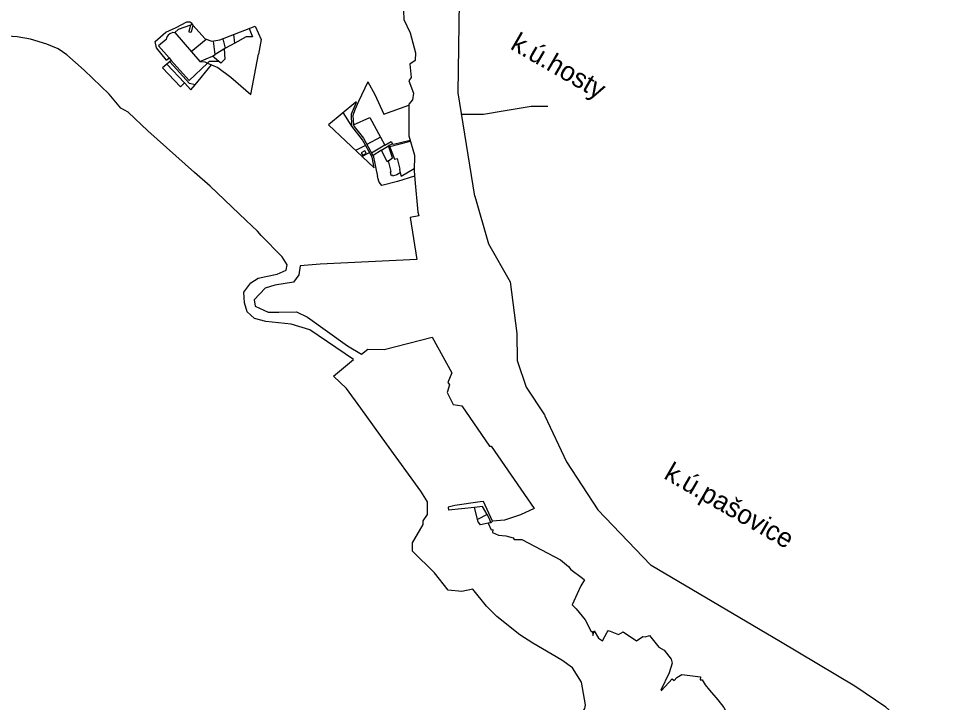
# Model space of a CAD drawing. Extents: x -764981 to -759318, y -1137368 to -1131930.
# Drawn here: x -762113 to -759967, y -1135485 to -1133883 of the extents above; entities that cross this region are included whole.
import ezdxf

# ---------------------------------------------------------------- set-up
doc = ezdxf.new("R2010")
doc.units = 0
for name, color, linetype in [('Vrstva 41', 7, 'Continuous'), ('Vrstva 42', 7, 'Continuous'), ('Vrstva 43', 7, 'Continuous'), ('Vrstva 44', 7, 'Continuous'), ('Vrstva 45', 7, 'Continuous')]:
    doc.layers.add(name, color=color, linetype=linetype)

msp = doc.modelspace()

# ---------------------------------------------------------------- linework, layer by layer
at = {"layer": 'Vrstva 41'}
for p, q in [((-761328.6, -1134681.5), (-761431.4, -1134612.5)), ((-761006.8, -1134884.9), (-760906.4, -1135030.1))]:
    msp.add_line(p, q, dxfattribs=at)
for points in [[(-761214.7, -1133846.5), (-761217.2, -1133856), (-761212.1, -1133865.8), (-761211.2, -1133885.6), (-761196.3, -1133917.4), (-761184.3, -1133963.9)], [(-762019.4, -1133954.7), (-762046.2, -1133943.4), (-762084.5, -1133932), (-762115.9, -1133926.8), (-762138.9, -1133924.6), (-762215.9, -1133917.4), (-762269.7, -1133912.3), (-762279.3, -1133912.3)], [(-761809.7, -1134146.5), (-761856.3, -1134102.7), (-761873.3, -1134093.2), (-761900.8, -1134060.9), (-761959.1, -1134004.8), (-761999.4, -1133968.5), (-762019.4, -1133954.7)], [(-761184.3, -1133963.9), (-761184.8, -1133982.2), (-761197.3, -1133990.7), (-761193.8, -1134021.8), (-761199.6, -1134029.3), (-761188.8, -1134058.5), (-761190.8, -1134074.1), (-761199.3, -1134084.3), (-761199.3, -1134158.4)], [(-761664.6, -1134276), (-761701.2, -1134244.3), (-761809.7, -1134146.5)], [(-761199.3, -1134158.4), (-761186.5, -1134203.1), (-761187.4, -1134239.8), (-761185.5, -1134260.3), (-761178.5, -1134336.9), (-761175.9, -1134345.7)], [(-761553.8, -1134381.2), (-761580.2, -1134356.1), (-761664.6, -1134276)], [(-761175.9, -1134345.7), (-761196.6, -1134349), (-761181, -1134447.9)], [(-761569.4, -1134502.6), (-761552.3, -1134491.6), (-761534.4, -1134487.6), (-761507.8, -1134481.7), (-761486.2, -1134472.7), (-761484.4, -1134460.1), (-761496, -1134441.7), (-761544.6, -1134391.5), (-761553.8, -1134381.2)], [(-761181, -1134447.9), (-761406.9, -1134458.7), (-761453.6, -1134462.4), (-761456.7, -1134483.4)], [(-761456.7, -1134483.4), (-761469.6, -1134500.8), (-761513.2, -1134507.8), (-761535.4, -1134515.1), (-761561.6, -1134541.8), (-761558.6, -1134557.1), (-761528.4, -1134570.6), (-761503.4, -1134570.6)], [(-761431.4, -1134612.5), (-761475, -1134598.7), (-761533.9, -1134592.7), (-761560.3, -1134585.7), (-761578, -1134569.9), (-761584, -1134549.1), (-761585.3, -1134524), (-761569.4, -1134502.6)], [(-761503.4, -1134570.6), (-761462.5, -1134570.2), (-761436.8, -1134582.4), (-761342.9, -1134649.4)], [(-761342.9, -1134649.4), (-761310.5, -1134669.2), (-761295.3, -1134657.5), (-761257.1, -1134658), (-761144.9, -1134629.3), (-761098.7, -1134712.6), (-761108.5, -1134735.5), (-761104.5, -1134741), (-761109.9, -1134759.1), (-761095.9, -1134786.9), (-761075.8, -1134790.4), (-761010.6, -1134884.9), (-761006.8, -1134884.9)], [(-761311.8, -1134795.4), (-761345.7, -1134749.2), (-761375.8, -1134721.1), (-761328.6, -1134681.5)], [(-761171.8, -1134989.8), (-761251.6, -1134879), (-761311.8, -1134795.4)], [(-761191.2, -1135127.7), (-761190.9, -1135110.7), (-761165.9, -1135067.7), (-761165.9, -1135059.2), (-761155.9, -1135044.2), (-761155.7, -1135015), (-761171.8, -1134989.8)], [(-760906.4, -1135030.1), (-760938, -1135045.2), (-760976, -1135057.6), (-761003.9, -1135060.2)], [(-761003.9, -1135060.2), (-761007.6, -1135063.8), (-761014.1, -1135065.1), (-761007.2, -1135080.5), (-761002.8, -1135079.8), (-761004.2, -1135086.6)], [(-761004.2, -1135086.6), (-760989.9, -1135093.1), (-760973, -1135094.3), (-760955.7, -1135098.8), (-760953, -1135102.7), (-760935.1, -1135103.1), (-760844.8, -1135150.3), (-760826.2, -1135166.4), (-760820.7, -1135173.2), (-760793, -1135193.7), (-760788.7, -1135197.3)], [(-761049.7, -1135219.1), (-761075.7, -1135224.7), (-761107.2, -1135221.8), (-761139.6, -1135181.2), (-761191.2, -1135130.4), (-761191.2, -1135127.7)], [(-760788.7, -1135197.3), (-760797.5, -1135211.4), (-760806, -1135230.5), (-760817.5, -1135256.2)], [(-760993.7, -1135283.2), (-761017.8, -1135259.1), (-761049.7, -1135219.1)], [(-760817.5, -1135256.2), (-760808, -1135265.5), (-760787.5, -1135291.3), (-760773, -1135318.5), (-760770.3, -1135318.1), (-760769, -1135327.9), (-760765.8, -1135316.6), (-760756.2, -1135333.7), (-760746.9, -1135340.5)], [(-760841.9, -1135385.5), (-760909.7, -1135346), (-760939.6, -1135326.4), (-760993.7, -1135283.2)], [(-760746.9, -1135340.5), (-760735.4, -1135320), (-760732.2, -1135315.8)], [(-760732.2, -1135315.8), (-760709.1, -1135325.3), (-760698.1, -1135319), (-760667.4, -1135340.2), (-760652.3, -1135329.9), (-760646.9, -1135330.6), (-760636.9, -1135327.4), (-760623.9, -1135343.7), (-760614.9, -1135354.9), (-760602.7, -1135362.1)], [(-760602.7, -1135362.1), (-760585.7, -1135383.4), (-760583.3, -1135392.4), (-760591, -1135415.1)], [(-760803.3, -1135523.4), (-760787.9, -1135499), (-760786.3, -1135490.3), (-760795.7, -1135437), (-760816.4, -1135403.3), (-760841.9, -1135385.5)], [(-760591, -1135415.1), (-760610, -1135455.9), (-760608.3, -1135456.7), (-760583.4, -1135429.2)], [(-760583.4, -1135429.2), (-760579, -1135433), (-760573.1, -1135426.3), (-760560.7, -1135419.1), (-760517.7, -1135424.4), (-760518, -1135431.3), (-760513.8, -1135431.5), (-760506.3, -1135443.6), (-760496.4, -1135455.5), (-760477.2, -1135478.4)], [(-760477.2, -1135478.4), (-760462.5, -1135496.3), (-760441.5, -1135532.6), (-760431.6, -1135537.7), (-760423.2, -1135539.2), (-760410, -1135574.4)]]:
    msp.add_lwpolyline(points, dxfattribs=at)
at = {"layer": 'Vrstva 42'}
for p, q in [((-761258.1, -1134107.6), (-761199.2, -1134086.1)), ((-761186.2, -1134252.8), (-761226.2, -1134264.7))]:
    msp.add_line(p, q, dxfattribs=at)
for points in [[(-761766.4, -1133980.7), (-761789.9, -1133952.3), (-761792.5, -1133937.6), (-761768.3, -1133915.7), (-761743.5, -1133904.7), (-761718.6, -1133891.5), (-761711.4, -1133891.5), (-761707.7, -1133893.3)], [(-761707.7, -1133893.3), (-761707.7, -1133895), (-761704.4, -1133899.5), (-761675.9, -1133931.1), (-761660.3, -1133936.9), (-761641.4, -1133933.6), (-761558.7, -1133901.3)], [(-761558.7, -1133901.3), (-761545.2, -1133932.5), (-761551.2, -1133966.8)], [(-761660.9, -1133992.1), (-761646.1, -1133998.2), (-761615.5, -1134020.8), (-761569.4, -1134061.4), (-761551.2, -1133966.8)], [(-761766.4, -1133980.7), (-761760.3, -1133975.5), (-761755.2, -1133981.6), (-761775.9, -1133998.8)], [(-761775.9, -1133998.8), (-761734, -1134043.4), (-761724.4, -1134034.4), (-761709.3, -1134050.5), (-761699.1, -1134038.7), (-761660.9, -1133992.1)], [(-761295.2, -1134031.7), (-761316.9, -1134078), (-761326.1, -1134097.5), (-761330.2, -1134110.6), (-761328.8, -1134132.6)], [(-761295.2, -1134031.7), (-761278.9, -1134061.4), (-761258.1, -1134107.6)], [(-761323.9, -1134079.7), (-761387.3, -1134132.5), (-761280.7, -1134233.4)], [(-761280.7, -1134233.4), (-761285.7, -1134208.3), (-761307.8, -1134167.3), (-761332.9, -1134135.4), (-761333.9, -1134106.3), (-761321.6, -1134079.2), (-761323.9, -1134079.7)], [(-761328.8, -1134132.6), (-761327.1, -1134136.4), (-761305.7, -1134163.7), (-761284.1, -1134204.3), (-761284.1, -1134204.3)], [(-761284.1, -1134204.3), (-761282.7, -1134204.3), (-761273, -1134253)], [(-761226.2, -1134264.7), (-761262.5, -1134274.7), (-761268.7, -1134266.7), (-761272.4, -1134256.7), (-761273, -1134253)], [(-761091.8, -1135023.7), (-761107.5, -1135027.6), (-761106.5, -1135034.6)], [(-761003.9, -1135060.2), (-761024.9, -1135014.4), (-761032.8, -1135014.6), (-761091.8, -1135023.7)], [(-761014.1, -1135065.1), (-761031.8, -1135068.8), (-761037.6, -1135061.8), (-761046, -1135028.3), (-761106.5, -1135034.6)]]:
    msp.add_lwpolyline(points, dxfattribs=at)
at = {"layer": 'Vrstva 43'}
for p, q in [((-761760.3, -1133975.5), (-761784.9, -1133947.3)), ((-761708.5, -1133960.5), (-761673.4, -1133931.9)), ((-761628, -1133952.6), (-761652.6, -1133967.7)), ((-761724.4, -1134034.4), (-761765.9, -1133990.6)), ((-761670.1, -1133987.8), (-761660.9, -1133992.1)), ((-761332.9, -1134135.4), (-761352.9, -1134103.8)), ((-761300.9, -1134180.7), (-761324.2, -1134192.2)), ((-761195.4, -1134171.8), (-761243.7, -1134183.9)), ((-761302.4, -1134193.6), (-761310.8, -1134198)), ((-761309.1, -1134206.7), (-761291.9, -1134197)), ((-761263.4, -1134191.8), (-761282.7, -1134204.3)), ((-761220.2, -1134244.9), (-761227.3, -1134249.1)), ((-761016.2, -1135044.3), (-761038.9, -1135056.2))]:
    msp.add_line(p, q, dxfattribs=at)
for points in [[(-761710.2, -1133899.1), (-761738.8, -1133909.5), (-761746.6, -1133916)], [(-761704.4, -1133899.5), (-761708.7, -1133898.5), (-761710.2, -1133899.1), (-761713.9, -1133913.7), (-761713.2, -1133913.9)], [(-761704.4, -1133899.5), (-761708.6, -1133915.6), (-761709.9, -1133915.2), (-761710.3, -1133916.6), (-761713.7, -1133915.7), (-761713.2, -1133913.9)], [(-761573.2, -1133907.2), (-761565.1, -1133926.8), (-761580, -1133926.7), (-761606.7, -1133941), (-761609.1, -1133921.2)], [(-761746.6, -1133916), (-761747.4, -1133916.8), (-761751.7, -1133916.6), (-761758.9, -1133919.6), (-761762.6, -1133922.3), (-761765, -1133925.8), (-761766.5, -1133929.7), (-761766.8, -1133932.5), (-761784.9, -1133947.3)], [(-761746.6, -1133916), (-761688.1, -1133984), (-761676.4, -1133984.6), (-761670.1, -1133987.8), (-761713.7, -1134028.7), (-761755.2, -1133981.6)], [(-761606.7, -1133941), (-761628, -1133952.6), (-761633.7, -1133930.8)], [(-761688.1, -1133984), (-761659.1, -1133971.8), (-761652.6, -1133967.7), (-761656.1, -1133936.4)], [(-761631.1, -1133954.5), (-761629.8, -1133978.9), (-761639.6, -1133987.9), (-761659.1, -1133971.8)], [(-761699.1, -1134038.7), (-761712.4, -1134036), (-761758.4, -1133985.1)], [(-761670.1, -1133987.8), (-761665.4, -1133983.7), (-761645, -1133983.5)], [(-761328.8, -1134132.6), (-761290.8, -1134115.1), (-761265.6, -1134161.1), (-761297.5, -1134178.6)], [(-761265.6, -1134161.1), (-761255.6, -1134179.8), (-761287.2, -1134198.6)], [(-761247, -1134217), (-761250.2, -1134219.3), (-761263.4, -1134191.8), (-761247.1, -1134181.4)], [(-761255.6, -1134179.8), (-761240.5, -1134171.8), (-761238, -1134176.6), (-761247.1, -1134181.4)], [(-761237.9, -1134209.7), (-761247.1, -1134181.4), (-761245.3, -1134179.9), (-761232.7, -1134212.5), (-761227.2, -1134211.5), (-761220.5, -1134236.4), (-761221.7, -1134236.7), (-761220.2, -1134244.9)], [(-761238, -1134176.6), (-761235.8, -1134178), (-761196.4, -1134168.5)], [(-761310.8, -1134198), (-761307.2, -1134203.9), (-761299.1, -1134198.9), (-761302.4, -1134193.6)], [(-761227.3, -1134249.1), (-761237.6, -1134252.9), (-761238.7, -1134250), (-761240.6, -1134250.7), (-761242.8, -1134242.1), (-761240.6, -1134241.5), (-761247, -1134217), (-761237.9, -1134209.7)], [(-761220.2, -1134244.9), (-761217.6, -1134252.2), (-761187.2, -1134234.9)], [(-761007.6, -1135063.8), (-761010.9, -1135054.8), (-761016.2, -1135044.3), (-761027.3, -1135025.5), (-761046, -1135028.3)]]:
    msp.add_lwpolyline(points, dxfattribs=at)
at = {"layer": 'Vrstva 44'}
for points in [[(-761045, -1134299.3), (-761084.5, -1134057.3), (-761080.8, -1133844), (-761084.5, -1133738.3)], [(-761045, -1134299.3), (-761013.2, -1134410.8), (-760962.5, -1134500), (-760946.8, -1134620.5), (-760946.3, -1134683.7), (-760925.1, -1134746.3), (-760882.5, -1134811.2), (-760881.6, -1134812.7)], [(-760881.6, -1134812.7), (-760881.3, -1134813.2), (-760830.8, -1134921.6), (-760757.7, -1135033.7), (-760634.3, -1135162), (-760633, -1135163.3)], [(-759967.4, -1135610.9), (-760014.2, -1135556.9), (-760084.2, -1135495.3), (-760156.5, -1135446.1), (-760330.3, -1135342.9), (-760632.5, -1135163.6), (-760633, -1135163.3)]]:
    msp.add_lwpolyline(points, dxfattribs=at)
at = {"layer": 'Vrstva 45'}
msp.add_line((-760913.6, -1134089), (-760874.3, -1134089), dxfattribs=at)
msp.add_lwpolyline([(-761075.7, -1134107.4), (-761025.3, -1134107.4), (-760974.4, -1134099), (-760913.6, -1134089)], dxfattribs=at)

# ---------------------------------------------------------------- texts
for s, p in [('k.ú.hosty', (-760964.5, -1133953.4)), ('k.ú.pašovice', (-760605.5, -1134958.9))]:
    msp.add_text(s, height=45, rotation=330, dxfattribs=at).set_placement(p)

doc.saveas('drawing.dxf')
